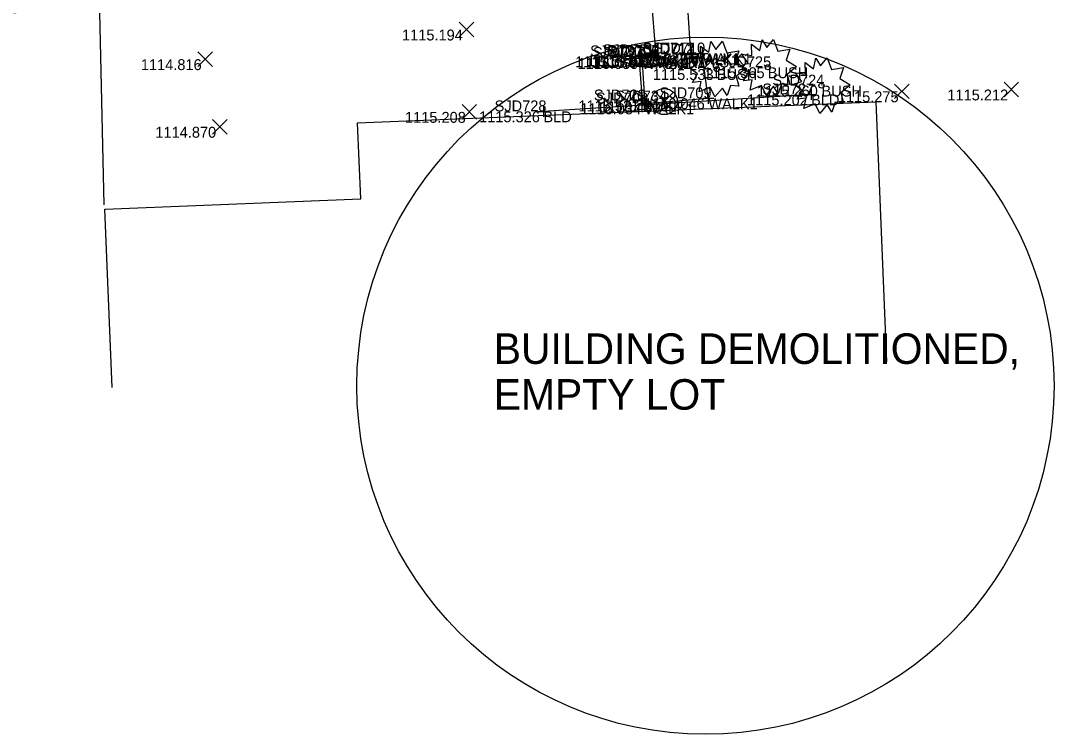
# Model space of a CAD drawing. Extents: x 1629915 to 1630675, y 484401 to 484601.
# Drawn here: x 1630554.5 to 1630649.4, y 484401.3 to 484466.8 of the extents above; entities that cross this region are included whole.
import ezdxf

# ---------------------------------------------------------------- set-up
doc = ezdxf.new("R2010")
doc.units = 0
for name, color, linetype in [('BD_X_Building', 7, 'Continuous'), ('BR_X_Sub_Foot_Object', 7, 'Continuous'), ('PV_X_Walk', 7, 'Continuous'), ('RD_X_RR_Cells', 7, 'Continuous'), ('SC_Scratch1', 7, 'Continuous'), ('SV_X_Break_Lines', 7, 'Continuous'), ('SV_X_Random_Point', 7, 'Continuous'), ('SV_X_Shot_Marker', 7, 'Continuous'), ('SV_X_Text_Comment', 7, 'Continuous'), ('SV_X_Text_Elevation', 7, 'Continuous'), ('SV_X_Text_Name', 7, 'Continuous'), ('VG_X_Cells', 7, 'Continuous')]:
    doc.layers.add(name, color=color, linetype=linetype)

msp = doc.modelspace()

# ---------------------------------------------------------------- linework, layer by layer
at = {"layer": 'BD_X_Building'}
for p, q in [((1630626.99, 484460.016), (1630602.444, 484458.465)), ((1630585.402, 484457.41), (1630632.966, 484459.353)), ((1630633.941, 484435.489), (1630632.966, 484459.353)), ((1630585.686, 484450.456), (1630585.402, 484457.41)), ((1630562.217, 484449.498), (1630585.686, 484450.456)), ((1630562.885, 484433.128), (1630562.217, 484449.498))]:
    msp.add_line(p, q, dxfattribs=at)
at = {"layer": 'BR_X_Sub_Foot_Object'}
msp.add_line((1630562.167, 484449.895), (1630560.47, 484522.988), dxfattribs=at)
at = {"layer": 'PV_X_Walk'}
msp.add_lwpolyline([(1630493.476, 484465.775), (1630510.562, 484466.345), (1630535.879, 484467.047), (1630568.892, 484467.942), (1630595.477, 484468.584), (1630612.287, 484469.275), (1630612.757, 484463.547), (1630612.783, 484463.442), (1630611.461, 484463.356), (1630611.74, 484459.193), (1630617.565, 484459.663), (1630617.01, 484463.773), (1630616.025, 484463.69), (1630615.968, 484463.775), (1630615.61, 484469.428), (1630634.527, 484469.698), (1630634.521, 484474.409), (1630639.35, 484473.673), (1630639.447, 484470.095), (1630649.394, 484470.376)], dxfattribs=at)
at = {"layer": 'RD_X_RR_Cells'}
for p, q in [((1630614.376, 484458.515), (1630612.679, 484460.212)), ((1630612.679, 484458.515), (1630614.376, 484460.212))]:
    msp.add_line(p, q, dxfattribs=at)
msp.add_circle((1630613.528, 484459.364), 1.2, dxfattribs=at)
at = {"layer": 'SC_Scratch1'}
msp.add_circle((1630617.308, 484433.297), 31.972, dxfattribs=at)
at = {"layer": 'SV_X_Break_Lines'}
msp.add_lwpolyline([(1630611.534, 484459.464), (1630611.215, 484463.506), (1630612.337, 484463.609)], dxfattribs=at)
at = {"layer": 'SV_X_Random_Point'}
for p, q in [((1630594.731, 484465.298), (1630596.064, 484466.633)), ((1630594.731, 484466.633), (1630596.064, 484465.298)), ((1630570.758, 484462.582), (1630572.092, 484463.917)), ((1630570.758, 484463.917), (1630572.092, 484462.582)), ((1630634.649, 484459.636), (1630635.982, 484460.971)), ((1630634.649, 484460.971), (1630635.982, 484459.636)), ((1630644.698, 484459.8), (1630646.031, 484461.135)), ((1630644.698, 484461.135), (1630646.031, 484459.8)), ((1630594.982, 484457.745), (1630596.315, 484459.08)), ((1630594.982, 484459.08), (1630596.315, 484457.745)), ((1630572.099, 484456.379), (1630573.432, 484457.714)), ((1630572.099, 484457.714), (1630573.432, 484456.379))]:
    msp.add_line(p, q, dxfattribs=at)
at = {"layer": 'SV_X_Shot_Marker'}
for p, q in [((1630615.968, 484464.275), (1630615.968, 484463.275)), ((1630616.025, 484464.19), (1630616.025, 484463.19)), ((1630617.01, 484464.273), (1630617.01, 484463.273)), ((1630610.715, 484463.506), (1630611.715, 484463.506)), ((1630610.961, 484463.356), (1630611.961, 484463.356)), ((1630611.215, 484464.006), (1630611.215, 484463.006)), ((1630611.215, 484463.506), (1630611.215, 484463.506)), ((1630611.461, 484463.856), (1630611.461, 484462.856)), ((1630611.461, 484463.356), (1630611.461, 484463.356)), ((1630611.837, 484463.609), (1630612.837, 484463.609)), ((1630612.257, 484463.547), (1630613.257, 484463.547)), ((1630612.283, 484463.442), (1630613.283, 484463.442)), ((1630612.337, 484464.109), (1630612.337, 484463.109)), ((1630612.337, 484463.609), (1630612.337, 484463.609)), ((1630612.757, 484464.047), (1630612.757, 484463.047)), ((1630612.757, 484463.547), (1630612.757, 484463.547)), ((1630612.783, 484463.942), (1630612.783, 484462.942)), ((1630612.783, 484463.442), (1630612.783, 484463.442)), ((1630615.468, 484463.775), (1630616.468, 484463.775)), ((1630615.525, 484463.69), (1630616.525, 484463.69)), ((1630615.968, 484463.775), (1630615.968, 484463.775)), ((1630616.025, 484463.69), (1630616.025, 484463.69)), ((1630616.51, 484463.773), (1630617.51, 484463.773)), ((1630617.01, 484463.773), (1630617.01, 484463.773)), ((1630626.99, 484460.516), (1630626.99, 484459.516)), ((1630611.034, 484459.464), (1630612.034, 484459.464)), ((1630611.534, 484459.964), (1630611.534, 484458.964)), ((1630611.534, 484459.464), (1630611.534, 484459.464)), ((1630611.74, 484459.693), (1630611.74, 484458.693)), ((1630617.065, 484459.663), (1630618.065, 484459.663)), ((1630617.565, 484460.163), (1630617.565, 484459.163)), ((1630617.565, 484459.663), (1630617.565, 484459.663)), ((1630626.49, 484460.016), (1630627.49, 484460.016)), ((1630626.99, 484460.016), (1630626.99, 484460.016)), ((1630602.444, 484458.965), (1630602.444, 484457.965)), ((1630611.24, 484459.193), (1630612.24, 484459.193)), ((1630611.74, 484459.193), (1630611.74, 484459.193)), ((1630601.944, 484458.465), (1630602.944, 484458.465)), ((1630602.444, 484458.465), (1630602.444, 484458.465))]:
    msp.add_line(p, q, dxfattribs=at)
at = {"layer": 'VG_X_Cells'}
for points in [[(1630618.255, 484464.153), (1630618.86, 484464.888), (1630619.275, 484463.835), (1630620.366, 484464.015), (1630620.028, 484463.003), (1630620.973, 484462.408), (1630620.116, 484461.673), (1630620.366, 484460.76), (1630619.613, 484460.828), (1630619.288, 484459.915), (1630618.86, 484460.606), (1630618.181, 484459.79), (1630617.753, 484460.676), (1630616.733, 484460.246), (1630616.925, 484461.188), (1630616.113, 484461.105), (1630616.586, 484461.895), (1630615.818, 484462.463), (1630616.556, 484462.726), (1630615.95, 484463.53), (1630616.881, 484463.42), (1630616.851, 484464.458), (1630617.605, 484463.89), (1630617.811, 484464.875), (1630618.255, 484464.153)], [(1630622.936, 484464.318), (1630623.541, 484465.053), (1630623.956, 484464), (1630625.048, 484464.18), (1630624.71, 484463.168), (1630625.655, 484462.573), (1630624.798, 484461.838), (1630625.048, 484460.925), (1630624.295, 484460.993), (1630623.97, 484460.08), (1630623.541, 484460.772), (1630622.863, 484459.955), (1630622.435, 484460.842), (1630621.415, 484460.412), (1630621.606, 484461.353), (1630620.795, 484461.27), (1630621.268, 484462.06), (1630620.5, 484462.628), (1630621.238, 484462.892), (1630620.631, 484463.695), (1630621.563, 484463.585), (1630621.533, 484464.623), (1630622.286, 484464.055), (1630622.493, 484465.04), (1630622.936, 484464.318)], [(1630627.86, 484462.636), (1630628.465, 484463.371), (1630628.88, 484462.318), (1630629.971, 484462.498), (1630629.633, 484461.486), (1630630.578, 484460.891), (1630629.721, 484460.156), (1630629.971, 484459.243), (1630629.218, 484459.311), (1630628.893, 484458.398), (1630628.465, 484459.089), (1630627.786, 484458.273), (1630627.358, 484459.159), (1630626.338, 484458.729), (1630626.53, 484459.671), (1630625.718, 484459.588), (1630626.191, 484460.378), (1630625.423, 484460.946), (1630626.161, 484461.209), (1630625.555, 484462.013), (1630626.486, 484461.903), (1630626.456, 484462.941), (1630627.21, 484462.373), (1630627.416, 484463.358), (1630627.86, 484462.636)]]:
    msp.add_lwpolyline(points, dxfattribs=at)
for centre in [(1630618.339, 484462.344), (1630623.021, 484462.509), (1630627.944, 484460.826)]:
    msp.add_circle(centre, 0.23, dxfattribs=at)

# ---------------------------------------------------------------- texts
at = {"layer": 'SC_Scratch1'}
for s, p in [('BUILDING DEMOLITIONED,', (1630597.892, 484435.3)), ('EMPTY LOT', (1630597.892, 484431.1))]:
    msp.add_text(s, height=2.8, dxfattribs=at).set_placement(p)
at = {"layer": 'SV_X_Text_Comment'}
for s, p in [('B10', (1630611.215, 484462.506)), ('WALK1', (1630611.461, 484462.356)), ('B10', (1630612.337, 484462.609)), ('WALK1', (1630612.757, 484462.547)), ('WALK1', (1630612.783, 484462.442)), ('WALK1', (1630615.968, 484462.775)), ('WALK1', (1630616.025, 484462.69)), ('WALK1', (1630617.01, 484462.773)), ('BUSH', (1630618.34, 484461.343)), ('BUSH', (1630623.021, 484461.508)), ('BUSH', (1630627.945, 484459.826)), ('B10', (1630611.534, 484458.464)), ('WALK1', (1630617.565, 484458.663)), ('BLD', (1630626.99, 484459.016)), ('WALK1', (1630611.74, 484458.193)), ('FF', (1630613.528, 484458.364)), ('BLD', (1630602.444, 484457.465))]:
    msp.add_text(s, height=1, dxfattribs=at).set_placement(p)
at = {"layer": 'SV_X_Text_Elevation'}
for s, p in [('1115.194', (1630589.477, 484464.966)), ('1114.816', (1630565.523, 484462.249)), ('1115.383', (1630605.353, 484462.506)), ('1116.059', (1630605.579, 484462.356)), ('1115.517', (1630606.443, 484462.609)), ('1115.622', (1630606.885, 484462.547)), ('1116.043', (1630606.921, 484462.442)), ('1115.773', (1630610.106, 484462.775)), ('1116.043', (1630610.163, 484462.69)), ('1116.063', (1630611.148, 484462.773)), ('1115.533', (1630612.478, 484461.343)), ('1115.365', (1630617.153, 484461.508)), ('1115.260', (1630622.033, 484459.826)), ('1115.212', (1630639.493, 484459.467)), ('1115.521', (1630605.654, 484458.464)), ('1116.046', (1630611.663, 484458.663)), ('1115.202', (1630621.119, 484459.016)), ('1115.275', (1630629.447, 484459.303)), ('1116.034', (1630605.82, 484458.193)), ('1116.480', (1630607.616, 484458.364)), ('1115.208', (1630589.75, 484457.413)), ('1115.326', (1630596.542, 484457.465)), ('1114.870', (1630566.854, 484456.046))]:
    msp.add_text(s, height=1, dxfattribs=at).set_placement(p)
at = {"layer": 'SV_X_Text_Name'}
for s, p in [('SJD730', (1630606.727, 484463.506)), ('SJD707', (1630606.99, 484463.356)), ('SJD731', (1630607.881, 484463.609)), ('SJD706', (1630608.304, 484463.442)), ('SJD705', (1630608.312, 484463.547)), ('SJD712', (1630611.52, 484463.775)), ('SJD711', (1630611.568, 484463.69)), ('SJD710', (1630612.522, 484463.773)), ('SJD726', (1630613.861, 484462.343)), ('SJD725', (1630618.576, 484462.508)), ('SJD724', (1630623.448, 484460.826)), ('SJD729', (1630607.075, 484459.464)), ('SJD709', (1630613.107, 484459.663)), ('SJD727', (1630622.52, 484460.016)), ('SJD728', (1630597.969, 484458.465)), ('SJD708', (1630607.265, 484459.193)), ('SJD734', (1630609.031, 484459.364))]:
    msp.add_text(s, height=1, dxfattribs=at).set_placement(p)

doc.saveas('drawing.dxf')
